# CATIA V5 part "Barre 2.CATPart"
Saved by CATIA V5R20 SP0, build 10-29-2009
Part number: Barre 3
Bounding box of the stored display mesh (mm): x -2.339 to 75.254, y 37.661 to 75.254, z 2.5 to 5
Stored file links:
  C:\Users\Admin\Desktop\IAO\Barre 2.CATPart
  C:\Users\Admin\Desktop\IAO\Ass_4barres.CATProduct
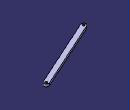
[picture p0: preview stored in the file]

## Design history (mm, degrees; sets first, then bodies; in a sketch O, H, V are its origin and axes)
Set1
  Sketch1 on Plane1, origin (0, 0, 0), H (1, 0, 0), V (0, 1, 0)
    construction line L1 (0, 40) -> (72.915, 72.915)
    point P1 (0, 40)
    point P2 (72.915, 72.915)
    line L2 (-1.0286, 42.2786) -> (71.8864, 75.1936)
    line L3 (73.9436, 70.6364) -> (1.0286, 37.7214)
    arc A1 centre (72.915, 72.915) radius 2.5 from (71.8864, 75.1936) to (73.9436, 70.6364) cw
    arc A2 centre (0, 40) radius 2.5 from (1.0286, 37.7214) to (-1.0286, 42.2786) cw
    reference projected point E1 (0, 40) from Point1
    reference projected point E2 (72.915, 72.915) from Point2
    distance L1 L2 = 2.5
    tangency: A1 L2, A2 L2, A1 L3, A2 L3
    coincidence: P1 E1, P2 E2
Set2
  Plane1 "Plan ref": linked copy from another document
  Point1 "Point B": linked copy from another document
  Point2 "Point C": linked copy from another document
Body1 (main body)
  Pad1: profile Sketch1, direction (0, 0, 1), length 5, opposite side length -2.5
  Sketch2 on start face of Pad1, origin (14.1146, 48.1849, 2.5), H (1, 0, 0), V (0, -1, 0)
    point P1 (-14.1146, 8.1849)
    reference projected arc E1 centre (-14.1146, 8.1849) radius 2.5 from (-15.1432, 10.4635) to (-13.086, 5.9064) ccw from edge [end face of Pad1 | face of Pad1 from Sketch1.A2]
    concentricity: P1 E1
  Hole1: placed by Sketch2, at (0, 40, 2.5) direction (0, 0, 1), diameter 2.5, through (limit type 6)
  Sketch3 on start face of Pad1, origin (73.9221, 71.324, 2.5), H (1, 0, 0), V (0, -1, 0)
    point P1 (-1.007, -1.591)
    reference projected arc E1 centre (-1.007, -1.591) radius 2.5 from (0.0215, -3.8696) to (-2.0356, 0.6876) ccw from edge [face of Pad1 from Sketch1.A1 | start face of Pad1]
    concentricity: P1 E1
  Hole2: placed by Sketch3, at (72.915, 72.915, 2.5) direction (0, 0, 1), diameter 2.5, through (limit type 6)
